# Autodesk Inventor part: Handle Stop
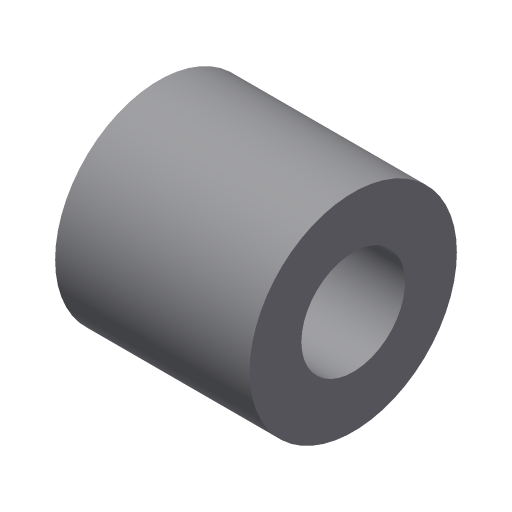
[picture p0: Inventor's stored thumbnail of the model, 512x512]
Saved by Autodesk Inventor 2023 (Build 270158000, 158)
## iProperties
Shininess: 77.0
Length Units: 11269
Angle Units: 11279
Time Units: 11290
Mass Units: 11283
Length Display Precision: 3
Angle Display Precision: 2
Compacted: True
Created: 2002-02
Part Number: Handle Stop
Document SubType Name: Modeling
Designer: ***
Density: 1 g/cm^3
Material: Generic
Appearance: Default
Density: 0.0
Volumn: 0.0
Area: 0.0
PropertySet Name: Model Information
Control State: 0
Master: False
Checked Out: False
Author: ***
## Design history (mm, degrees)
sketch "Sketch1"
  geometry: L1 (0, 0)-(0, -2); L2 (0, -2)-(8, -2); L3 (8, -2)-(8, 13); L4 (8, 13)-(4, 13); L5 (4, 13)-(4, 0); L6 (4, 0)-(0, 0)
  constraints: 12 end point, 4 parallel, 1 perpendicular, 1 vertical
  dimensions: "d0" = 16 diameter of L3 L1; "d1" = 8 diameter of L5 L1; "d2" = 2 distance of L1.start L1.end; "d3" = 15 distance of L2.end L3.end
revolve "Revolution1" sketch "Sketch1" stored, may be unused: angle "d4" = 90 deg
body "Solid1"
